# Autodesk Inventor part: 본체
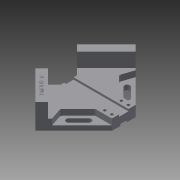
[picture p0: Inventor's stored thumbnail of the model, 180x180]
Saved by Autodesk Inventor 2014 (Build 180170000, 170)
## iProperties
Created: 2019-04
Part Number: 본체
Material: Generic
Document SubType Name: Modeling
Designer: kh
Density: 1 g/cm^3
Appearance: Default
Mass: 222.781 g
Surface Area: 426.536 cm^2
Volume: 222.781 cm^3
Author: kh
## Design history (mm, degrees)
sketch "Sketch1"
  geometry: L1 (0, 47.99)-(0, -172.536); L2 (0, 0)-(-14.005, 0); L3 (-14.005, 0)-(-35.355, 21.35); L4 (-35.355, 21.35)-(-84.853, -28.147); L5 (-84.853, -28.147)-(-20, -93); L6 (-20, -93)-(0, -93); L7 (-35.355, 21.35)-(0, 56.706); L8 (-20, -93)-(0, -113); L9 (0, 0)-(14.005, 0); L10 (14.005, 0)-(35.355, 21.35); L11 (35.355, 21.35)-(84.853, -28.147); L12 (84.853, -28.147)-(20, -93); L13 (20, -93)-(0, -93); L14 (35.355, 21.35)-(0, 56.706); L15 (20, -93)-(0, -113); 1 further point
  constraints: 30 end point, 6 point on line, 4 perpendicular, 4 symmetric about line, 1 collinear, 1 parallel, 1 vertical
  dimensions: "d0" = 50 distance of L3.end L7.end; "d1" = 120 distance of L7.end L4.end; "d2" = 120 distance of L8.end L4.end; "d3" = 20 horizontal distance of L8.end L5.end; "d4" = 93 distance of L6.end L2.start
extrude "Extrusion1" new body sketch "Sketch1" distance "d5" = 18; taper "d6" = 0 deg
sketch "Sketch2"
  geometry: L1 (-35.355, 21.35)-(-84.853, -28.147) reference; L2 (-14.005, 0)-(-35.355, 21.35) reference; L3 (-35.355, 21.35)-(-84.853, -28.147); L4 (-74.246, -38.754)-(-24.749, 10.744); L5 (-35.355, 21.35)-(-24.749, 10.744); L6 (-84.853, -28.147)-(-20, -93) reference; L7 (-84.853, -28.147)-(-74.246, -38.754); 1 further point
  constraints: 8 end point, 3 collinear, 1 perpendicular, 1 point on line
  dimensions: "d7" = 15 distance of L1.start L4.end
extrude "Extrusion2" join sketch "Sketch2" distance "d8" = 24; taper "d9" = 0 deg
mirror "Mirror1"
sketch "Sketch3"
  geometry: L1 (-8, 0)-(8, 0); L2 (8, 0)-(8, -93); L3 (8, -93)-(-8, -93); L4 (-8, -93)-(-8, 0); L5 (14.005, 0)-(-14.005, 0) reference; L6 (-20, -93)-(20, -93) reference; 3 further points
  constraints: 8 end point, 4 midpoint, 2 parallel, 1 horizontal, 1 perpendicular
  dimensions: "d10" = 16 distance of L1.start L1.end
extrude "Extrusion3" cut sketch "Sketch3" distance "d11" = 3.5; taper "d12" = 0 deg
sketch "Sketch4"
  geometry: L1 (-6, 0)-(6, 0); L2 (6, 0)-(6, -93); L3 (6, -93)-(-6, -93); L4 (-6, -93)-(-6, 0); L5 (-14.005, 0)-(14.005, 0) reference; L6 (20, -93)-(-20, -93) reference; 3 further points
  constraints: 8 end point, 4 midpoint, 2 parallel, 1 horizontal, 1 perpendicular
  dimensions: "d13" = 12 distance of L1.start L1.end
extrude "Extrusion4" cut sketch "Sketch4" distance "d14" = 3; taper "d15" = 0 deg
sketch "Sketch5"
  geometry: L1 (-74.246, -38.754)-(-20, -93) reference; L2 (-49.497, -35.218)-(-20, -64.716); L3 (-67.175, -31.683)-(-12.929, -85.929); L4 (-49.497, -49.36)-(-32.527, -66.331); L5 (-52.679, -52.542)-(-35.709, -69.513); L6 (-29.345, -63.149)-(-46.315, -46.178); L7 (-35.355, 21.35)-(-84.853, -28.147) reference; L8 (-70.711, -42.289)-(-49.497, -35.218); L9 (-20, -93)-(-20, -64.716); L10 (-70.711, -42.289)-(-20, -93); A1 r 4.5 centre (-49.497, -49.36) between (-46.315, -46.178) and (-52.679, -52.542); A2 r 4.5 centre (-32.527, -66.331) between (-35.709, -69.513) and (-29.345, -63.149); 2 further points
  constraints: 18 end point, 4 point on circle, 4 tangent, 3 parallel, 3 point on line, 2 centre point, 1 collinear, 1 midpoint, 1 vertical
  dimensions: "d16" = 20 distance between parallel lines of L1 L2; "d17" = 10 distance between parallel lines of L1 L3; "d19" = 24 distance of L4.end L4.start; "d20" = 40 distance from line of L4.start L7; "d22" = 20 distance from line of L8.start L7; "d23" = 30 distance from line of L2.start L7; "d24" = 9 diameter of A2
extrude "Extrusion5" cut sketch "Sketch5" distance "d25" = 10; taper "d26" = 0 deg
extrude "Extrusion6" cut sketch "Sketch5" stored distance "d27" = 10; taper "d28" = 0 deg
mirror "Mirror2"
mirror "Mirror3"
sketch "Sketch7"
  geometry: L1 (-8, -93)-(-20, -93) reference; 3 further points
  dimensions: "d32" = 6 distance from line of L1 point (-14, -87); "d33" = 12 distance of point (-14, -87) point (-14, -75); "d34" = 14 horizontal distance of point (0, 0) point (-14, -87); "d35" = 14 horizontal distance of point (0, 0) point (-14, -75)
hole "Hole1" sketch "Sketch7" at (-14, -75), (-14, -87) diameter "d36" = 4.5; stored, may be unused: countersink angle "d40" = 90 deg, drill point angle "d42" = 118 deg; dims "d37" = 6, "d38" = 8, "d39" = 10, "d41" = 8
mirror "Mirror4"
sketch "Sketch8"
  geometry: L1 (-35.829, 1.657)-(-65.159, -27.673); L2 (-65.159, -27.673)-(-73.772, -19.06); L3 (-73.772, -19.06)-(-44.442, 10.27); L4 (-44.442, 10.27)-(-35.829, 1.657); L5 (-35.355, 21.35)-(-84.853, -28.147) reference; L6 (-35.829, 1.657)-(-73.772, -19.06); L7 (-14.005, 0)-(-24.749, 10.744) reference; 2 further points
  constraints: 2 end point, 1 midpoint, 1 parallel, 2 other
  dimensions: "d43" = 35 distance from line of point (-54.801, -8.702) L7; "d44" = 7.5 distance from line of L5 point (-54.801, -8.702)
emboss "Emboss1" sketch "Sketch8" dims "d45" = 0.5, "d46" = 0
fillet "Fillet1" dims "d47" = 5
body "Solid1"
